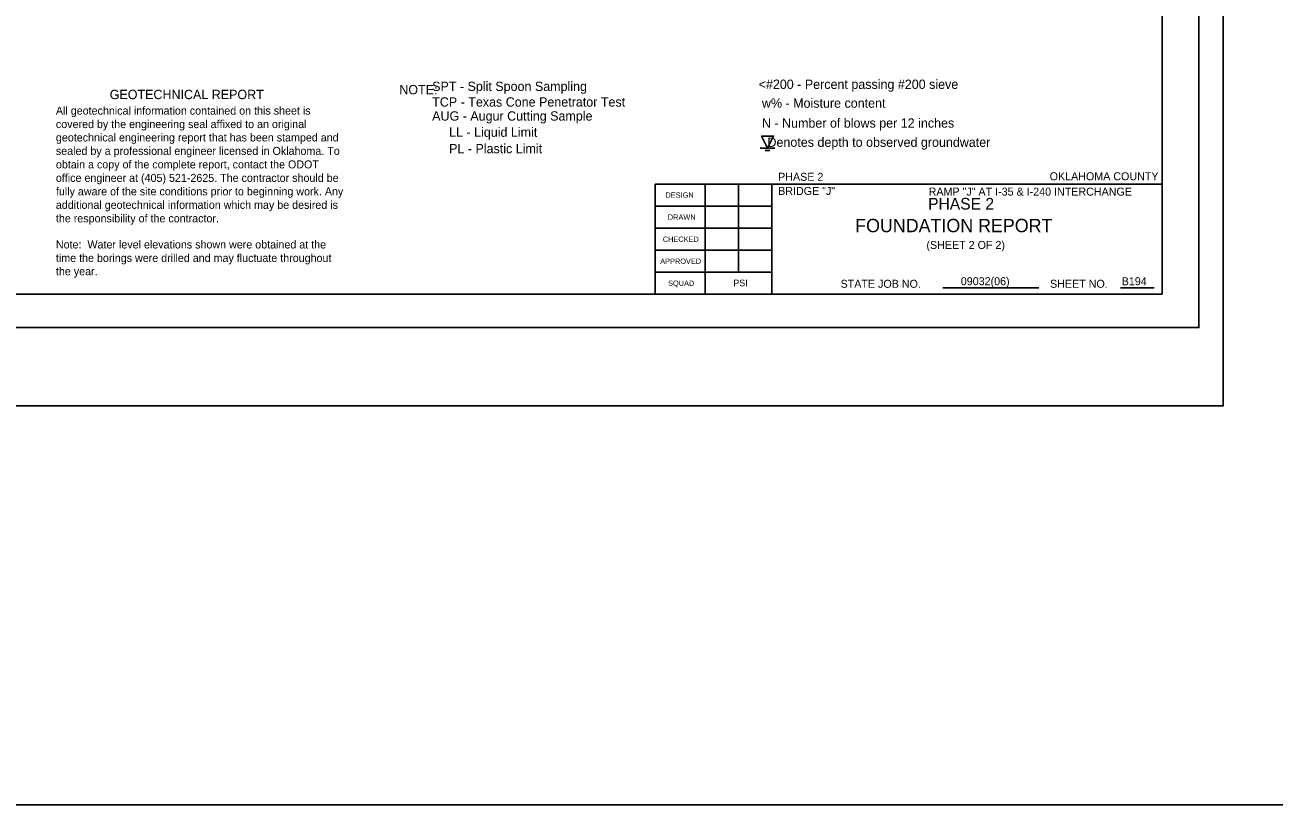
# Model space of a CAD drawing. Extents: x 2150148.6 to 2150220.1, y 143803.7 to 143875.1.
# Drawn here: x 2150182.61 to 2150201.34, y 143803.71 to 143815.4 of the extents above; entities that cross this region are included whole.
import ezdxf

# ---------------------------------------------------------------- set-up
doc = ezdxf.new("R2010")
doc.units = 0
for name, color, linetype in [('Default', 7, 'Continuous'), ('S', 7, 'Continuous'), ('SHT_Plot_Shape_Full', 7, 'Continuous'), ('SHT_Plot_Shape_Half', 7, 'Continuous'), ('SHT_Sheet_Border', 7, 'Continuous'), ('SHT_Standard_Sheet_Lines', 7, 'Continuous'), ('SHT_Standard_Sheet_Txt', 7, 'Continuous'), ('T', 7, 'Continuous'), ('T-Title', 7, 'Continuous'), ('Text', 7, 'Continuous')]:
    doc.layers.add(name, color=color, linetype=linetype)

# ---------------------------------------------------------------- blocks, each defined once
blk = doc.blocks.new('DGRFC_WTLEV1')
at = {"layer": 'Default'}
for points in [[(-0.0127, 0), (0.0127, 0)], [(0, 0), (0.0106, 0.0212), (-0.0106, 0.0212), (0, 0)], [(-0.0042, -0.0042), (0.0042, -0.0042)]]:
    blk.add_lwpolyline(points, dxfattribs=at)

msp = doc.modelspace()

# ---------------------------------------------------------------- linework, layer by layer
at = {"layer": 'S'}
msp.add_lwpolyline([(2150160.321, 143875.14), (2150220.06, 143875.14), (2150220.06, 143803.708), (2150160.321, 143803.708)], close=True, dxfattribs=at)
at = {"layer": 'SHT_Plot_Shape_Full'}
msp.add_lwpolyline([(2150164.575, 143833.688), (2150200.575, 143833.688), (2150200.575, 143809.688), (2150164.575, 143809.688)], close=True, dxfattribs=at)
at = {"layer": 'SHT_Plot_Shape_Half'}
msp.add_lwpolyline([(2150166.212, 143832.863), (2150200.212, 143832.863), (2150200.212, 143810.863), (2150166.212, 143810.863)], close=True, dxfattribs=at)
at = {"layer": 'SHT_Sheet_Border'}
for p, q in [((2150192.062, 143811.363), (2150192.062, 143813.013)), ((2150192.062, 143813.013), (2150199.662, 143813.013)), ((2150193.812, 143811.363), (2150193.812, 143813.014))]:
    msp.add_line(p, q, dxfattribs=at)
msp.add_lwpolyline([(2150199.662, 143811.363), (2150168.162, 143811.363), (2150168.162, 143832.363), (2150199.662, 143832.363)], close=True, dxfattribs=at)
at = {"layer": 'SHT_Standard_Sheet_Lines'}
for p, q in [((2150192.812, 143811.363), (2150192.812, 143813.014)), ((2150193.312, 143811.693), (2150193.312, 143813.014)), ((2150196.373, 143811.459), (2150197.813, 143811.459)), ((2150199.038, 143811.459), (2150199.54, 143811.459))]:
    msp.add_line(p, q, dxfattribs=at)
for points in [[(2150193.812, 143812.683), (2150192.062, 143812.683)], [(2150193.812, 143812.353), (2150192.062, 143812.353)], [(2150193.812, 143812.023), (2150192.062, 143812.023)], [(2150193.812, 143811.693), (2150192.062, 143811.693)]]:
    msp.add_lwpolyline(points, dxfattribs=at)

# ---------------------------------------------------------------- block references
at = {"layer": 'Default', "xscale": 8.503919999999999, "yscale": 8.503919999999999}
msp.add_blockref('DGRFC_WTLEV1', (2150193.745, 143813.553), dxfattribs=at)

# ---------------------------------------------------------------- texts
at = {"layer": 'Defpoints'}
msp.add_text('PHASE 2', height=0.175, dxfattribs=at).set_placement((2150196.152, 143812.631))
at = {"layer": 'SHT_Standard_Sheet_Txt'}
for s, height, p in [('DESIGN', 0.08, (2150192.215, 143812.808)), ('DRAWN', 0.08, (2150192.25, 143812.478)), ('CHECKED', 0.08, (2150192.175, 143812.147)), ('APPROVED', 0.08, (2150192.136, 143811.817)), ('SQUAD', 0.08, (2150192.254, 143811.487)), ('STATE JOB NO.', 0.12, (2150194.84, 143811.459)), ('SHEET NO. ', 0.12, (2150197.98, 143811.459))]:
    msp.add_text(s, height=height, dxfattribs=at).set_placement(p)
at = {"layer": 'T'}
for s, height, p in [('PHASE 2', 0.12, (2150193.904, 143813.062)), ('OKLAHOMA COUNTY', 0.12, (2150197.974, 143813.07)), ('BRIDGE "J"', 0.12, (2150193.904, 143812.85)), ('RAMP "J" AT I-35 & I-240 INTERCHANGE', 0.12, (2150196.16, 143812.84)), ('(SHEET 2 OF 2)', 0.12, (2150196.127, 143812.041)), ('PSI', 0.1, (2150193.232, 143811.481)), ('09032(06)', 0.12, (2150196.642, 143811.497)), ('B194', 0.12, (2150199.054, 143811.497))]:
    msp.add_text(s, height=height, dxfattribs=at).set_placement(p)
at = {"layer": 'T-Title'}
msp.add_text('FOUNDATION REPORT', height=0.2, dxfattribs=at).set_placement((2150195.059, 143812.292))
at = {"layer": 'Text'}
for s, height, p in [('NOTE:', 0.14, (2150188.226, 143814.358)), ('    SPT - Split Spoon Sampling', 0.14, (2150188.51, 143814.408)), (' <#200 - Percent passing #200 sieve', 0.14, (2150193.56, 143814.439)), ('GEOTECHNICAL REPORT', 0.14, (2150183.885, 143814.286)), ('    TCP - Texas Cone Penetrator Test', 0.14, (2150188.51, 143814.174)), ('w% - Moisture content', 0.14, (2150193.661, 143814.157)), ('All geotechnical information contained on this sheet is ', 0.12, (2150183.078, 143814.054)), ('    AUG - Augur Cutting Sample', 0.14, (2150188.51, 143813.964)), ('covered by the engineering seal affixed to an original ', 0.12, (2150183.078, 143813.852)), ('N - Number of blows per 12 inches', 0.14, (2150193.661, 143813.858)), ('geotechnical engineering report that has been stamped and ', 0.12, (2150183.078, 143813.652)), (' LL - Liquid Limit', 0.14, (2150188.92, 143813.722)), ('    Denotes depth to observed groundwater', 0.14, (2150193.536, 143813.571)), ('sealed by a professional engineer licensed in Oklahoma. To ', 0.12, (2150183.078, 143813.45)), (' PL - Plastic Limit', 0.14, (2150188.92, 143813.475)), ('obtain a copy of the complete report, contact the ODOT ', 0.12, (2150183.078, 143813.248)), ('office engineer at (405) 521-2625. The contractor should be ', 0.12, (2150183.078, 143813.046)), ('fully aware of the site conditions prior to beginning work. Any ', 0.12, (2150183.078, 143812.844)), ('additional geotechnical information which may be desired is ', 0.12, (2150183.078, 143812.642)), ('the responsibility of the contractor.', 0.12, (2150183.078, 143812.44)), ('Note:  Water level elevations shown were obtained at the ', 0.12, (2150183.078, 143812.048)), ('time the borings were drilled and may fluctuate throughout ', 0.12, (2150183.078, 143811.846)), ('the year.', 0.12, (2150183.078, 143811.646))]:
    msp.add_text(s, height=height, dxfattribs=at).set_placement(p)

doc.saveas('drawing.dxf')
